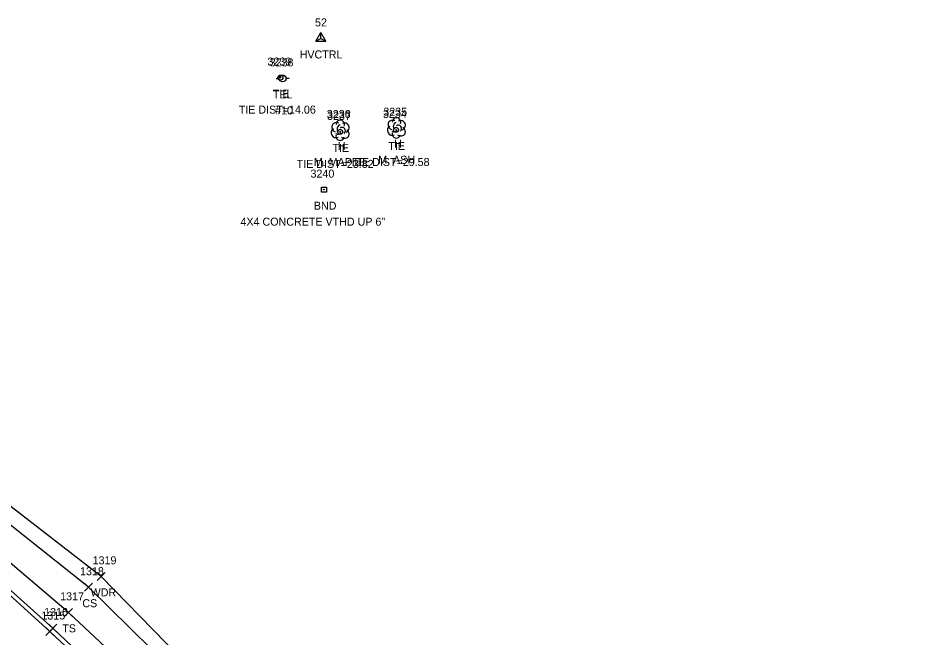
# Model space of a CAD drawing. Extents: x 1647574 to 1652703, y 212895 to 228670.
# Drawn here: x 1649361.4 to 1649589.7, y 226878.8 to 227033.5 of the extents above; entities that cross this region are included whole.
import ezdxf

# ---------------------------------------------------------------- set-up
doc = ezdxf.new("R2010")
doc.units = 0
for name, color, linetype in [('C_A', 7, 'Continuous'), ('C_C', 7, 'Continuous'), ('C_I', 7, 'Continuous'), ('CBP', 7, 'Continuous'), ('CPSM', 7, 'Continuous'), ('L_A', 7, 'Continuous'), ('L_C', 7, 'Continuous'), ('L_I', 7, 'Continuous'), ('L_TIC', 7, 'Continuous'), ('LAWA', 7, 'Continuous'), ('LELB', 7, 'Continuous'), ('LTD', 7, 'Continuous'), ('M_A', 7, 'Continuous'), ('M_C', 7, 'Continuous'), ('M_I', 7, 'Continuous'), ('MHBP', 7, 'Continuous'), ('P_I', 7, 'Continuous'), ('P_TIC', 7, 'Continuous'), ('PSP', 7, 'Continuous'), ('R_I', 7, 'Continuous'), ('R_TIC', 7, 'Continuous'), ('RGR', 7, 'Continuous'), ('U_A', 7, 'Continuous'), ('U_C', 7, 'Continuous'), ('U_I', 7, 'Continuous'), ('UP', 7, 'Continuous')]:
    doc.layers.add(name, color=color, linetype=linetype)

msp = doc.modelspace()

# ---------------------------------------------------------------- linework, layer by layer
at = {"layer": 'CBP'}
for centre, radius in [((1649426.91, 227018.67), 0.625), ((1649426.91, 227018.67), 0.0833), ((1649441.81, 227005.12), 0.625), ((1649441.81, 227005.12), 0.0833), ((1649455.78, 227005.59), 0.625), ((1649455.78, 227005.59), 0.0833)]:
    msp.add_circle(centre, radius, dxfattribs=at)
at = {"layer": 'CPSM'}
for p, q in [((1649435.76, 227027.73), (1649437.01, 227029.89)), ((1649438.26, 227027.73), (1649437.01, 227029.89)), ((1649437.01, 227028.45), (1649437.01, 227029.89)), ((1649435.76, 227027.73), (1649437.01, 227028.45)), ((1649435.76, 227027.73), (1649438.26, 227027.73)), ((1649437.01, 227028.45), (1649437.01, 227028.45)), ((1649437.01, 227028.45), (1649438.26, 227027.73))]:
    msp.add_line(p, q, dxfattribs=at)
at = {"layer": 'L_TIC'}
for points in [[(1649381.09, 226893.12), (1649383.09, 226895.12)], [(1649383.09, 226893.12), (1649381.09, 226895.12)], [(1649377.95, 226890.41), (1649379.95, 226892.41)], [(1649379.95, 226890.41), (1649377.95, 226892.41)], [(1649372.97, 226884.13), (1649374.97, 226886.13)], [(1649374.97, 226884.13), (1649372.97, 226886.13)]]:
    msp.add_lwpolyline(points, dxfattribs=at)
at = {"layer": 'LAWA'}
msp.add_lwpolyline([(1649620.52, 226666.86), (1649581.67, 226703.66), (1649547.28, 226735.48), (1649514.21, 226767.75), (1649480.07, 226801.7), (1649444.95, 226835.57), (1649408.03, 226867.53), (1649382.09, 226894.12), (1649349.21, 226919.43), (1649317.07, 226948.87), (1649283.57, 226984.27), (1649262.7, 226991.58)], dxfattribs=at)
at = {"layer": 'LELB'}
for points in [[(1649611.68, 226660.43), (1649573.8, 226694.76), (1649539.29, 226728.48), (1649506.26, 226759.21), (1649471.69, 226791.64), (1649437.47, 226825.67), (1649400.06, 226860.66), (1649373.97, 226885.13), (1649343.06, 226911.31), (1649307.79, 226942.26), (1649266.92, 226975.01), (1649262.13, 226979.91), (1649252.93, 226990.96)], [(1650010.63, 226272.18), (1649976.36, 226308.87), (1649944.85, 226340.83), (1649916.6, 226368.96), (1649885.58, 226401.45), (1649851.41, 226433.71), (1649822.12, 226460.28), (1649782.98, 226498.9), (1649750.04, 226529.83), (1649718.83, 226559.66), (1649689.09, 226593.62), (1649652.01, 226632.5), (1649616.85, 226664.27), (1649578.69, 226701.52), (1649544.7, 226732.63), (1649511.82, 226765.51), (1649477.06, 226797.14), (1649442.21, 226831.27), (1649405.15, 226865.62), (1649378.95, 226891.41), (1649346.59, 226917.07), (1649311.19, 226946.22)]]:
    msp.add_lwpolyline(points, dxfattribs=at)
at = {"layer": 'LTD'}
for p, q in [((1649441.8, 227005.57), (1649441.8, 227005.57)), ((1649441.8, 227005.57), (1649441.8, 227005.57)), ((1649455.86, 227006.15), (1649455.86, 227006.15)), ((1649455.86, 227006.15), (1649455.86, 227006.15))]:
    msp.add_line(p, q, dxfattribs=at)
for centre in [(1649441.85, 227007), (1649455.91, 227007.58)]:
    msp.add_arc(centre, 1.05, 335.5272, 180.9563, dxfattribs=at)
for centre, major_axis, ratio, start_param, end_param in [((1649441.01, 227006.23), (1.21, -0.51), 0.895232, 1.570796, 4.712389), ((1649441.6, 227006.02), (-0.208, -0.792), 0.645439, 3.141593, 6.283185), ((1649442.85, 227006.15), (-1.14, -0.48), 0.949671, 1.570796, 4.712389), ((1649455.07, 227006.81), (1.21, -0.51), 0.895232, 1.570796, 4.712389), ((1649455.65, 227006.61), (-0.208, -0.792), 0.645439, 3.141593, 6.283185), ((1649456.36, 227005.98), (-0.5, 0.667), 0.989748, 3.141593, 6.283185), ((1649456.9, 227006.73), (-1.14, -0.48), 0.949671, 1.570796, 4.712389), ((1649440.72, 227004.86), (0.58, -1.04), 0.959034, 3.141593, 6.283185), ((1649441.8, 227004.07), (0.26, 1.06), 0.942809, 1.570796, 4.712389), ((1649441.35, 227004.82), (-0.625, -0.083), 0.423636, 0, 3.141593), ((1649442.3, 227005.4), (-0.5, 0.667), 0.989748, 3.141593, 6.283185), ((1649442.8, 227004.73), (-1.09, 0.79), 0.841452, 1.570796, 4.712389), ((1649454.78, 227005.44), (0.58, -1.04), 0.959034, 3.141593, 6.283185), ((1649455.86, 227004.65), (0.26, 1.06), 0.942809, 1.570796, 4.712389), ((1649455.4, 227005.4), (-0.625, -0.083), 0.423636, 0, 3.141593), ((1649456.86, 227005.31), (-1.09, 0.79), 0.841452, 1.570796, 4.712389)]:
    msp.add_ellipse(centre, major_axis=major_axis, ratio=ratio, start_param=start_param, end_param=end_param, dxfattribs=at)
at = {"layer": 'MHBP'}
msp.add_lwpolyline([(1649437.14, 226991.32), (1649438.39, 226991.32), (1649438.39, 226990.07), (1649437.14, 226990.07)], close=True, dxfattribs=at)
msp.add_circle((1649437.76, 226990.69), 0.0833, dxfattribs=at)
at = {"layer": 'P_TIC'}
for points in [[(1649368.29, 226879.34), (1649370.29, 226881.34)], [(1649370.29, 226879.34), (1649368.29, 226881.34)]]:
    msp.add_lwpolyline(points, dxfattribs=at)
at = {"layer": 'PSP'}
msp.add_lwpolyline([(1649606.95, 226655.87), (1649570.92, 226690.01), (1649534.66, 226724.21), (1649502.87, 226754.78), (1649467.98, 226787.83), (1649433.22, 226820.15), (1649395.45, 226855.86), (1649369.29, 226880.34), (1649338.69, 226908.03), (1649304.51, 226937.47), (1649274.58, 226964.09), (1649261.77, 226975.07), (1649262.11, 226976.25), (1649259.14, 226977.14), (1649257.68, 226977.62), (1649243.4, 226991.01), (1649239.83, 226990.77), (1649218.05, 226994.51), (1649195.64, 226998.51), (1649190.94, 226999.11)], dxfattribs=at)
at = {"layer": 'R_TIC'}
for points in [[(1649369.04, 226880.22), (1649371.04, 226882.22)], [(1649371.04, 226880.22), (1649369.04, 226882.22)]]:
    msp.add_lwpolyline(points, dxfattribs=at)
at = {"layer": 'RGR'}
msp.add_lwpolyline([(1649607.54, 226656.38), (1649571.29, 226690.65), (1649535.2, 226725), (1649503.13, 226755.54), (1649468.46, 226788.77), (1649433.73, 226820.87), (1649396.03, 226856.51), (1649370.04, 226881.22), (1649339.35, 226908.59), (1649304.93, 226938.03), (1649276.23, 226963.71), (1649262.11, 226976.25)], dxfattribs=at)
at = {"layer": 'UP'}
for p, q in [((1649425.79, 227018.46), (1649426.61, 227018.46)), ((1649427.45, 227018.47), (1649427.45, 227018.47)), ((1649429.11, 227018.47), (1649428.28, 227018.47)), ((1649428.28, 227018.47), (1649428.28, 227018.47)), ((1649429.11, 227018.47), (1649429.11, 227018.47))]:
    msp.add_line(p, q, dxfattribs=at)
msp.add_circle((1649427.45, 227018.47), 0.833, dxfattribs=at)

# ---------------------------------------------------------------- texts
at = {"layer": 'C_A'}
for s, p in [('HVCTRL', (1649431.7, 227023.45)), ('TIE', (1649424.99, 227013.67)), ('TIE', (1649439.89, 227000.12)), ('TIE', (1649453.86, 227000.59))]:
    msp.add_text(s, height=2, dxfattribs=at).set_placement(p)
at = {"layer": 'C_C'}
for s, p in [('TIE DIST=14.06', (1649416.48, 227009.67)), ('TIE DIST=23.82', (1649430.95, 226996.12)), ('TIE DIST=29.58', (1649444.91, 226996.59))]:
    msp.add_text(s, height=2, dxfattribs=at).set_placement(p)
at = {"layer": 'C_I'}
for s, p in [('52', (1649435.54, 227031.45)), ('3239', (1649423.65, 227021.67)), ('3237', (1649438.55, 227008.12)), ('3234', (1649452.52, 227008.59))]:
    msp.add_text(s, height=2, dxfattribs=at).set_placement(p)
at = {"layer": 'L_A'}
for s, p in [('H', (1649441.24, 227000.57)), ('H', (1649455.29, 227001.15)), ('WDR', (1649379.46, 226889.12)), ('CS', (1649377.39, 226886.41)), ('TS', (1649372.38, 226880.13))]:
    msp.add_text(s, height=2, dxfattribs=at).set_placement(p)
at = {"layer": 'L_C'}
for s, p in [('M. MAPLE', (1649435.25, 226996.57)), ('M. ASH', (1649451.33, 226997.15))]:
    msp.add_text(s, height=2, dxfattribs=at).set_placement(p)
at = {"layer": 'L_I'}
for s, p in [('3235', (1649452.6, 227009.15)), ('3236', (1649438.49, 227008.57)), ('1319', (1649379.96, 226897.12)), ('1318', (1649376.82, 226894.41)), ('1317', (1649371.85, 226888.13))]:
    msp.add_text(s, height=2, dxfattribs=at).set_placement(p)
at = {"layer": 'M_A'}
msp.add_text('BND', height=2, dxfattribs=at).set_placement((1649435.25, 226985.69))
at = {"layer": 'M_C'}
msp.add_text('4X4 CONCRETE VTHD UP 6"', height=2, dxfattribs=at).set_placement((1649416.91, 226981.69))
at = {"layer": 'M_I'}
msp.add_text('3240', height=2, dxfattribs=at).set_placement((1649434.42, 226993.69))
at = {"layer": 'P_I'}
msp.add_text('1315', height=2, dxfattribs=at).set_placement((1649367.16, 226883.34))
at = {"layer": 'R_I'}
msp.add_text('1316', height=2, dxfattribs=at).set_placement((1649367.85, 226884.22))
at = {"layer": 'U_A'}
msp.add_text('TEL', height=2, dxfattribs=at).set_placement((1649425.01, 227013.47))
at = {"layer": 'U_C'}
msp.add_text('#10', height=2, dxfattribs=at).set_placement((1649425.57, 227009.47))
at = {"layer": 'U_I'}
msp.add_text('3238', height=2, dxfattribs=at).set_placement((1649424.19, 227021.47))

doc.saveas('drawing.dxf')
